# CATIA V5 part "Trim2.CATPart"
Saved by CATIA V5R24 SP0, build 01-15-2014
Part number: Part1
Bounding box of the stored display mesh (mm): x 0 to 0, y -130 to -30, z -180 to -75.359
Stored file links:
  E:\Desktop_RNH\학부 CAD 수업 자료\[CAD_V2]강의자료(CAD)_2017년 이후\툴바예제\4 GSD\Operations\Trim22.CATPart
  E:\users\spu\Gsd R10\TrimKeepRemove.CATPart
  E:\Desktop_RNH\학부 CAD 수업 자료\[CAD_V2]강의자료(CAD)_2017년 이후\툴바예제\4 GSD\Operations\Trim2.CATPart
  E:\Desktop_RNH\학부 CAD 수업 자료\[CAD_V2]강의자료(CAD)_2017년 이후\툴바예제\4 GSD\Operations\Trim1.CATPart

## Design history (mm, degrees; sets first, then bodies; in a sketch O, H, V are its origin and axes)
Set1 "Standard Trim"
  Set2 "Geometrical Set.2"
    Point1: type OnPlane, Support xy-plane, H 51.714, V 36.189, Direction (1, 0, 0)
    Point2: type OnPlane, Support xy-plane, H 132.41, V 53.422, Direction (1, 0, 0)
    Line1: type PtPt, FirstPoint Point2, SecondPoint Point1
    Sketch1 "Sketch.2" on xy-plane, origin (0, 0, 0), H (1, 0, 0), V (0, 1, 0)
      line L1 (230, 200) -> (230, 120)
      line L2 (230, 120) -> (250, 120)
      line L3 (250, 120) -> (250, 170)
      point P4 (250, 170)
      spline S1 through (250, 170) (260, 180) (270, 170)
      line L4 (270, 170) -> (270, 120)
      line L5 (270, 120) -> (280, 120)
      line L6 (280, 120) -> (290, 120)
      line L7 (290, 120) -> (290, 170)
      point P8 (290, 170)
      point P9 (270, 170)
      spline S2 through (290, 170) (300, 180) (310, 170)
      line L8 (310, 170) -> (310, 130)
      line L9 (310, 130) -> (310, 120)
      point P11 (310, 120)
      line L10 (310, 120) -> (330, 120)
      point P13 (310, 170)
      line L11 (330, 120) -> (330, 170)
      point P14 (330, 170)
      spline S3 through (330, 170) (340, 180) (350, 170)
      point P15 (350, 120)
      line L12 (350, 120) -> (370, 120)
      line L13 (370, 120) -> (370, 220)
      line L14 (370, 220) -> (230, 220)
      point P18 (230, 220)
      line L15 (230, 220) -> (230, 200)
      line L16 (350, 170) -> (350, 120)
      point P19 (350, 170)
      point P20 (250, 170)
      point P21 (270, 170)
      point P22 (290, 170)
      point P23 (310, 170)
      point P24 (330, 170)
      point P25 (350, 170)
      vertical: L1 V, L3 V, L4 V, L7 V, L8 V, L9 V, L11 V, L13 V, L15 V, L16 V
      horizontal: L2 H, L5 H, L6 H, L10 H, L12 H, L14 H
      coincidence: P20 P4, P21 P9, P22 P8, P11 L6, P23 P13, P24 P14, P15 L10, P18 L1, P25 P19
    Set3
      Point3 "Point.1": stored without definition
      Circle1: type CtrRad, Start 13, End 168, Center Point3, Support yz-plane, Radius 30, FirstDirection (0, 1, 0)
      Circle2: type CtrRad, Start 13, End 168, Center {point type OnPlane, Support yz-plane, H -100, V -130, Direction (0, 1, 0)}, Support yz-plane, Radius 30, FirstDirection (0, 1, 0)
      Circle3: type CtrRad, Start 13, End 168, Center {point type OnPlane, Support yz-plane, H -60, V -150, Direction (0, 1, 0)}, Support yz-plane, Radius 30, FirstDirection (0, 1, 0)
Body1 (main body)
  Pad1: profile Sketch1, direction (0, 0, 1), length 20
